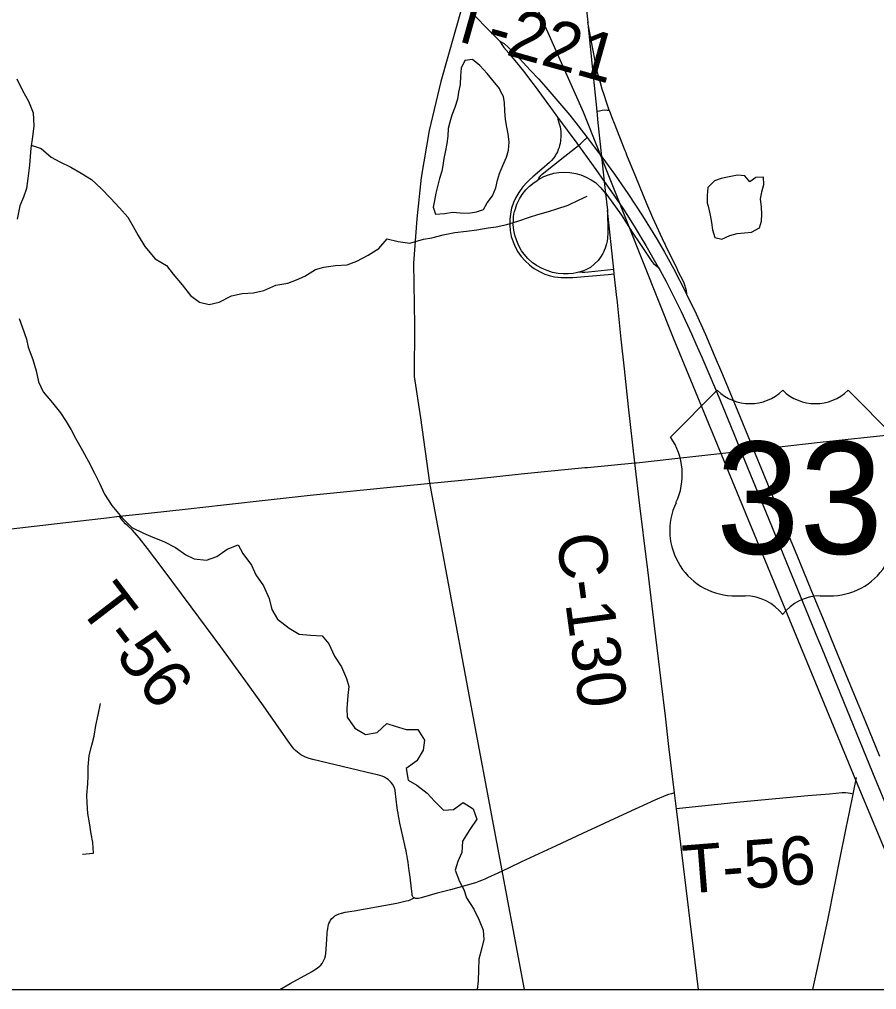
# Model space of a CAD drawing. Extents: x -5.9 to 34, y 0 to 22.
# Drawn here: x 5.923 to 7.938, y 14 to 16.281 of the extents above; entities that cross this region are included whole.
import ezdxf

# ---------------------------------------------------------------- set-up
doc = ezdxf.new("R2010")
doc.units = 0
for name, color, linetype in [('GM_X_County_Road', 7, 'Continuous'), ('GM_X_County_Road_Text', 7, 'Continuous'), ('GM_X_Interchange_Ramps', 7, 'Continuous'), ('GM_X_Minor_Lake', 7, 'Continuous'), ('GM_X_Minor_River', 7, 'Continuous'), ('GM_X_Rail_Line', 7, 'Continuous'), ('GM_X_State_Route', 7, 'Continuous'), ('GM_X_Township_Road', 7, 'Continuous'), ('GM_X_Township_Road_Text', 7, 'Continuous'), ('GM_X_US_Route', 7, 'Continuous'), ('GM_X_US_Shield', 7, 'Continuous'), ('SH_Data', 7, 'Continuous')]:
    doc.layers.add(name, color=color, linetype=linetype)

msp = doc.modelspace()

# ---------------------------------------------------------------- linework, layer by layer
at = {"layer": 'GM_X_County_Road'}
msp.add_line((7.4675, 14.4252), (7.463, 14.4624), dxfattribs=at)
for points in [[(7.3278, 15.6228), (7.3274, 15.6268), (7.3213, 15.6824), (7.3203, 15.6929), (7.3054, 15.8323)], [(7.3449, 15.4594), (7.3371, 15.5291), (7.3278, 15.6228)], [(7.3982, 15.0005), (7.3977, 15.0045), (7.3809, 15.1377), (7.3696, 15.2383), (7.3548, 15.3698), (7.3449, 15.4594)], [(7.6189, 15.2659), (7.6487, 15.269), (7.709, 15.2759), (7.8054, 15.287), (7.9228, 15.2994), (8.0205, 15.3095), (8.0959, 15.3177), (8.1247, 15.321)], [(7.2522, 15.2272), (7.2582, 15.2278), (7.3696, 15.2383), (7.3732, 15.2386), (7.4633, 15.2489), (7.6189, 15.2659)], [(5.9038, 15.0835), (6.0323, 15.0983), (6.1212, 15.1086), (6.158, 15.1127), (6.2262, 15.1203), (6.32, 15.1306), (6.4028, 15.1399), (6.5151, 15.1521), (6.6066, 15.1621), (6.7945, 15.1809), (7.0023, 15.2017), (7.1024, 15.2123), (7.2522, 15.2272)], [(7.463, 14.4624), (7.4498, 14.5716), (7.4415, 14.6432), (7.4316, 14.7258), (7.4158, 14.8553), (7.3982, 15.0005)], [(7.7881, 14), (7.8016, 14.0615), (7.8121, 14.1126), (7.8229, 14.1636), (7.8398, 14.2464), (7.8522, 14.3098), (7.8662, 14.3792), (7.8743, 14.4169), (7.8827, 14.4596), (7.8906, 14.499)], [(7.519, 14), (7.4996, 14.1609), (7.487, 14.2645), (7.4775, 14.3422), (7.4675, 14.4252)]]:
    msp.add_lwpolyline(points, dxfattribs=at)
at = {"layer": 'GM_X_Interchange_Ramps'}
for points in [[(7.3096, 16.0674), (7.3028, 16.0861), (7.2971, 16.1039), (7.2929, 16.1169), (7.2887, 16.1317), (7.2851, 16.1443), (7.282, 16.1562), (7.2793, 16.169), (7.2765, 16.1819), (7.2747, 16.1915), (7.2724, 16.2037), (7.2701, 16.2156), (7.2588, 16.2743)], [(7.1881, 16.0509), (7.1887, 16.046), (7.1899, 16.0406), (7.1924, 16.0331), (7.1937, 16.0285), (7.1949, 16.0231), (7.1955, 16.0175), (7.1958, 16.012), (7.1959, 16.0063), (7.195, 15.9952), (7.194, 15.989), (7.1928, 15.9842), (7.1915, 15.9796), (7.1897, 15.9748), (7.1877, 15.9699), (7.1855, 15.9658), (7.1823, 15.9604), (7.1788, 15.9553), (7.1735, 15.9489), (7.1689, 15.9443), (7.151, 15.9289), (7.1301, 15.9111), (7.1222, 15.904), (7.1167, 15.8982), (7.1059, 15.8862), (7.0971, 15.8742), (7.09, 15.8625), (7.0843, 15.8501), (7.0799, 15.8372), (7.077, 15.8238), (7.0755, 15.8103), (7.0754, 15.7966), (7.0766, 15.7842), (7.0792, 15.7708), (7.0832, 15.7577), (7.088, 15.7463), (7.0946, 15.7343), (7.1025, 15.7232), (7.1116, 15.713), (7.1217, 15.7038), (7.1273, 15.6995), (7.1327, 15.6956), (7.1387, 15.692), (7.1455, 15.688), (7.1579, 15.6823), (7.1685, 15.6787), (7.1806, 15.6757), (7.1882, 15.6745), (7.1954, 15.6739), (7.2033, 15.6738), (7.2127, 15.6738), (7.2242, 15.6744), (7.307, 15.6812), (7.3213, 15.6824)], [(7.1414, 15.9033), (7.144, 15.9078), (7.1461, 15.911), (7.1483, 15.9137), (7.1519, 15.917), (7.2048, 15.9593), (7.237, 15.9845), (7.241, 15.9877), (7.2441, 15.9905), (7.2482, 15.9945), (7.2572, 16.0033)], [(7.3203, 15.6929), (7.2607, 15.6865), (7.2519, 15.6857), (7.2454, 15.6856), (7.2383, 15.6867)]]:
    msp.add_lwpolyline(points, dxfattribs=at)
at = {"layer": 'GM_X_Minor_Lake'}
for points in [[(7.0549, 16.1107), (7.0511, 16.1182), (7.0362, 16.1366), (7.0228, 16.1535), (7.0049, 16.1721), (6.9877, 16.1868), (6.9702, 16.184), (6.9616, 16.1666), (6.9598, 16.1477), (6.9588, 16.1279), (6.9554, 16.1098), (6.9529, 16.0931), (6.9466, 16.0734), (6.9395, 16.0561), (6.9347, 16.0394), (6.9307, 16.0243), (6.9297, 16.0061), (6.9279, 15.9894), (6.9238, 15.969), (6.9205, 15.9538), (6.918, 15.9371), (6.9163, 15.9243)], [(6.9163, 15.9243), (6.9107, 15.9069), (6.9059, 15.888), (6.9019, 15.8721), (6.8986, 15.8554), (6.8953, 15.8395), (6.9012, 15.8227), (6.9224, 15.8247), (6.9414, 15.8274), (6.9588, 15.8264), (6.9785, 15.8253), (6.9975, 15.8281), (7.0135, 15.8339), (7.0221, 15.8497), (7.0352, 15.8662), (7.043, 15.8851), (7.0471, 15.9032), (7.0511, 15.9184), (7.059, 15.9372), (7.0676, 15.9569), (7.0724, 15.9735), (7.0742, 15.9925), (7.0722, 16.0115), (7.0687, 16.0275), (7.0659, 16.0458), (7.0639, 16.0656), (7.0634, 16.0845), (7.0606, 16.0998), (7.0549, 16.1107)], [(7.6672, 15.8707), (7.6681, 15.8754), (7.6729, 15.8928), (7.6717, 15.9103), (7.6542, 15.9091), (7.6397, 15.8987), (7.6278, 15.9133), (7.6111, 15.9143), (7.5914, 15.9108), (7.5724, 15.9065), (7.5564, 15.9015), (7.541, 15.8857), (7.5399, 15.8668), (7.5397, 15.8493), (7.5416, 15.8418)], [(7.5416, 15.8418), (7.5468, 15.8203), (7.5496, 15.8036), (7.5524, 15.7861), (7.5574, 15.7685), (7.574, 15.7645), (7.5931, 15.7725), (7.6098, 15.7776), (7.6273, 15.7788), (7.644, 15.7808), (7.6623, 15.7912), (7.6671, 15.8063), (7.6681, 15.823), (7.6676, 15.8397), (7.6649, 15.8588), (7.6672, 15.8707)]]:
    msp.add_lwpolyline(points, dxfattribs=at)
at = {"layer": 'GM_X_Minor_River'}
for points in [[(5.9172, 16.1412), (5.9303, 16.1137), (5.9443, 16.0884), (5.9552, 16.0609), (5.957, 16.0305), (5.9535, 16.0047), (5.9501, 15.9782), (5.9482, 15.9585), (5.9471, 15.938), (5.9428, 15.907), (5.9394, 15.8835), (5.9323, 15.8631), (5.9244, 15.8428), (5.9178, 15.811)], [(5.951, 15.9853), (5.9743, 15.977), (5.9974, 15.9569), (6.0184, 15.9459), (6.0439, 15.9334), (6.0679, 15.9193), (6.0927, 15.9045), (6.115, 15.8836), (6.1373, 15.8604), (6.1582, 15.8381), (6.1782, 15.8157), (6.1908, 15.7943), (6.2025, 15.7728), (6.218, 15.7467), (6.2425, 15.7182), (6.2687, 15.7026), (6.2843, 15.6819), (6.3058, 15.6572), (6.3251, 15.6318), (6.346, 15.6163), (6.3694, 15.6106), (6.3929, 15.6163), (6.4219, 15.631), (6.447, 15.6366), (6.4735, 15.6377), (6.4978, 15.6434), (6.526, 15.6558), (6.5541, 15.6606), (6.5747, 15.6686), (6.5938, 15.6774), (6.619, 15.6929), (6.6388, 15.6987), (6.6661, 15.702), (6.6933, 15.7038), (6.7162, 15.7125), (6.7429, 15.7265), (6.7681, 15.742), (6.7874, 15.7652), (6.8131, 15.7587), (6.841, 15.7545), (6.8729, 15.7645), (6.8927, 15.7673), (6.9193, 15.7744), (6.9466, 15.78), (6.9739, 15.7833), (6.9982, 15.786), (7.0247, 15.7908), (7.0437, 15.7935), (7.0688, 15.7984), (7.0946, 15.8063), (7.122, 15.8158), (7.1418, 15.8222), (7.1669, 15.8294), (7.1859, 15.8359), (7.2125, 15.8438), (7.2385, 15.8563), (7.2576, 15.8651)], [(5.9223, 15.5779), (5.9296, 15.558), (5.9397, 15.529), (5.9439, 15.51), (5.9548, 15.4817), (5.9627, 15.455), (5.9683, 15.4291), (5.9785, 15.4054), (6.0008, 15.3792), (6.0193, 15.3561), (6.0326, 15.3354), (6.0444, 15.3163), (6.0547, 15.2963), (6.0716, 15.2672), (6.0856, 15.2412), (6.0995, 15.2144), (6.1112, 15.1907), (6.1229, 15.1647), (6.1406, 15.1378), (6.1636, 15.1101), (6.1875, 15.0862), (6.2145, 15.0728), (6.237, 15.0633), (6.2626, 15.0538), (6.2896, 15.0397), (6.3143, 15.0218), (6.3338, 15.0124), (6.3625, 15.0096), (6.3869, 15.0183), (6.4114, 15.0353), (6.4373, 15.0455), (6.4483, 15.0249), (6.4683, 14.998), (6.4785, 14.975), (6.497, 14.9489), (6.5101, 14.9191), (6.5165, 14.8932), (6.5298, 14.8709), (6.5567, 14.85), (6.5807, 14.8352), (6.6071, 14.8332), (6.6343, 14.832)], [(6.6343, 14.832), (6.6507, 14.8127), (6.6638, 14.7837), (6.6801, 14.7591), (6.6917, 14.7316), (6.6975, 14.7125), (6.6948, 14.6913), (6.6928, 14.661), (6.6932, 14.6405), (6.7117, 14.6144), (6.7365, 14.5996), (6.7638, 14.6044), (6.7868, 14.6253), (6.8064, 14.6196), (6.832, 14.6116), (6.8593, 14.6112), (6.8748, 14.5866), (6.8721, 14.5631), (6.8573, 14.5376), (6.832, 14.5198), (6.8369, 14.4924), (6.8571, 14.4807), (6.8818, 14.4621), (6.8989, 14.4428), (6.9197, 14.422), (6.9432, 14.4231), (6.9662, 14.4401), (6.9894, 14.4253), (6.9981, 14.4009), (6.9818, 14.3761), (6.9647, 14.3491), (6.9627, 14.3226), (6.9533, 14.3015), (6.9476, 14.2811), (6.9578, 14.2544), (6.9673, 14.2352), (6.9738, 14.2154), (6.9908, 14.1893), (7.004, 14.1633), (7.0127, 14.1396), (7.0146, 14.1176), (7.0097, 14.0979), (7.0032, 14.0715), (7.002, 14.0465), (7.0016, 14.0207), (6.9988, 14)], [(6.0711, 14.3186), (6.0969, 14.3204), (6.0958, 14.3455), (6.0916, 14.366), (6.0875, 14.3919), (6.084, 14.414), (6.0822, 14.4383), (6.0817, 14.4573), (6.0837, 14.4838), (6.0848, 14.5027), (6.0844, 14.524), (6.0871, 14.5505), (6.0935, 14.5747), (6.0984, 14.5959), (6.1026, 14.6208), (6.1083, 14.6458), (6.1133, 14.6723)]]:
    msp.add_lwpolyline(points, dxfattribs=at)
at = {"layer": 'GM_X_Rail_Line'}
for points in [[(7.0415, 16.5495), (6.963, 16.3092), (6.9134, 16.1347), (6.8861, 16.02), (6.8674, 15.9094), (6.8568, 15.8119), (6.8493, 15.7081), (6.852, 15.5617), (6.8512, 15.4414), (6.8655, 15.3442), (6.8872, 15.1912), (6.9793, 14.6929), (7.1092, 14)], [(7.0415, 16.5495), (7.1132, 16.3672), (7.2481, 16.0636), (7.4593, 15.532), (7.8977, 14.4706), (8.0854, 14.0203), (8.0937, 14)]]:
    msp.add_lwpolyline(points, dxfattribs=at)
at = {"layer": 'GM_X_State_Route'}
for points in [[(7.2497, 16.3582), (7.2588, 16.2743), (7.2591, 16.2715), (7.2702, 16.1627), (7.2801, 16.0651), (7.2829, 16.0378), (7.2914, 15.9583), (7.2977, 15.8999), (7.3009, 15.8715), (7.3054, 15.8323)], [(7.2801, 16.0651), (7.2861, 16.0662), (7.2929, 16.0675), (7.2986, 16.0681), (7.3046, 16.0677), (7.3096, 16.0674), (7.3181, 16.044), (7.3194, 16.0405), (7.3209, 16.0368), (7.3462, 15.9723), (7.348, 15.9677), (7.3503, 15.9622), (7.3714, 15.9114), (7.3973, 15.8482), (7.4114, 15.815), (7.4387, 15.7558), (7.4405, 15.7518), (7.4418, 15.749), (7.4681, 15.695), (7.4717, 15.6875), (7.4766, 15.6776), (7.4836, 15.664), (7.4866, 15.6568), (7.4887, 15.6494), (7.4899, 15.6436), (7.4913, 15.6349)], [(7.2959, 15.7339), (7.2942, 15.7303), (7.2892, 15.7217), (7.2832, 15.7138), (7.2743, 15.7051), (7.265, 15.6979), (7.2543, 15.6922), (7.2462, 15.6889), (7.2383, 15.6867), (7.2316, 15.6847), (7.2243, 15.6837), (7.2126, 15.6828), (7.2009, 15.6828), (7.1897, 15.6836), (7.1763, 15.6861), (7.1632, 15.6902), (7.1518, 15.6951), (7.1387, 15.7023), (7.1286, 15.7095), (7.1184, 15.7186), (7.1093, 15.7288), (7.1035, 15.7369), (7.0966, 15.7487), (7.0918, 15.7602), (7.0877, 15.7733), (7.0852, 15.7854), (7.0839, 15.7978), (7.084, 15.809), (7.0846, 15.8168), (7.0854, 15.8226), (7.0868, 15.8294), (7.0887, 15.8359), (7.0924, 15.8464), (7.0984, 15.8588), (7.105, 15.8693), (7.1135, 15.88), (7.1221, 15.889), (7.1327, 15.8976), (7.1414, 15.9033), (7.1431, 15.9044), (7.1555, 15.9112), (7.1663, 15.9155), (7.179, 15.9192), (7.1911, 15.9212), (7.2044, 15.9217), (7.217, 15.9207), (7.2306, 15.9187), (7.2428, 15.9154), (7.2551, 15.9102), (7.2669, 15.9039), (7.2767, 15.8971), (7.2835, 15.891), (7.29, 15.8847), (7.3006, 15.8718)], [(7.3011, 15.8713), (7.3139, 15.8546), (7.3382, 15.8204), (7.3636, 15.781), (7.3814, 15.7544), (7.4063, 15.7164), (7.4094, 15.7119), (7.4135, 15.7073), (7.4179, 15.7029), (7.421, 15.7006), (7.4245, 15.6987)], [(7.3054, 15.8323), (7.3061, 15.7793), (7.3055, 15.7669), (7.3045, 15.7597), (7.3031, 15.7535), (7.2998, 15.7428), (7.2975, 15.7375), (7.2959, 15.7339)]]:
    msp.add_lwpolyline(points, dxfattribs=at)
at = {"layer": 'GM_X_Township_Road'}
msp.add_line((7.4675, 14.4252), (7.463, 14.4624), dxfattribs=at)
for points in [[(6.8512, 14.2154), (6.8494, 14.2163), (6.848, 14.2177), (6.8469, 14.2199), (6.8463, 14.2223), (6.8459, 14.2246), (6.8435, 14.2437), (6.8405, 14.2703), (6.8395, 14.2795), (6.8387, 14.2858), (6.8378, 14.2921), (6.8366, 14.2998), (6.8354, 14.3073), (6.8343, 14.3134), (6.8331, 14.3202), (6.8319, 14.3261), (6.8305, 14.332), (6.8289, 14.3395), (6.8173, 14.3916), (6.8156, 14.4003), (6.8141, 14.4086), (6.813, 14.4151), (6.8119, 14.4221), (6.8105, 14.4332), (6.8095, 14.4411), (6.8087, 14.4469), (6.808, 14.4541), (6.8073, 14.4603), (6.8061, 14.4685), (6.8044, 14.4735), (6.8027, 14.4776), (6.7997, 14.4829), (6.7966, 14.4868), (6.7936, 14.49), (6.79, 14.4936), (6.7861, 14.4964), (6.7812, 14.4992), (6.7754, 14.5014), (6.7649, 14.5047), (6.7539, 14.5076), (6.701, 14.52), (6.6126, 14.5409), (6.6038, 14.5433), (6.5958, 14.5463), (6.589, 14.5494), (6.5845, 14.5519), (6.5804, 14.5547), (6.5765, 14.5578), (6.5723, 14.562), (6.5687, 14.5656), (6.5647, 14.5702), (6.5544, 14.5842), (6.4969, 14.6668), (6.4506, 14.7314), (6.3965, 14.8058), (6.3269, 14.8995), (6.2589, 14.9912), (6.2244, 15.0368), (6.2046, 15.0618), (6.1886, 15.0797), (6.1778, 15.0901), (6.1725, 15.0952), (6.1672, 15.1015), (6.1626, 15.1071), (6.158, 15.1127)], [(7.463, 14.4624), (7.4557, 14.4603), (7.4487, 14.4583), (7.4424, 14.4561), (7.4167, 14.4454), (7.3518, 14.4156), (7.2464, 14.3669), (7.1845, 14.338), (7.1029, 14.3004), (7.0724, 14.2858)], [(7.8827, 14.4596), (7.8766, 14.4608), (7.8711, 14.4619), (7.8644, 14.4625), (7.8567, 14.4623), (7.8273, 14.4595), (7.7765, 14.4553), (7.617, 14.4409), (7.4742, 14.4259), (7.4675, 14.4252)], [(7.0724, 14.2858), (7.0473, 14.2739), (7.0232, 14.2626), (7.0173, 14.2598), (7.0089, 14.2563), (7.0031, 14.2539), (6.9989, 14.2522), (6.9953, 14.2511), (6.9366, 14.2349), (6.905, 14.2265), (6.8675, 14.2155), (6.8641, 14.2148), (6.8608, 14.2142), (6.8587, 14.214), (6.8566, 14.2141), (6.8541, 14.2144), (6.8512, 14.2154)], [(6.5348, 14), (6.5591, 14.014), (6.6094, 14.042), (6.6169, 14.0465), (6.623, 14.0506), (6.6277, 14.0542), (6.6313, 14.0577), (6.6345, 14.0617), (6.6371, 14.066), (6.6388, 14.0691), (6.6406, 14.0735), (6.6423, 14.0792), (6.6432, 14.0847), (6.6449, 14.1059), (6.6463, 14.131), (6.6466, 14.1351), (6.647, 14.1383), (6.6476, 14.1433), (6.6487, 14.1486), (6.6498, 14.1528), (6.6507, 14.1556), (6.6523, 14.1591), (6.6545, 14.1629), (6.6575, 14.1668), (6.6609, 14.1702), (6.6647, 14.1733), (6.6692, 14.1761), (6.6745, 14.1783), (6.6803, 14.18), (6.6885, 14.1817), (6.71, 14.1855), (6.8104, 14.2032), (6.8322, 14.2084), (6.8372, 14.2097), (6.8413, 14.2112), (6.8481, 14.2141), (6.8512, 14.2154)]]:
    msp.add_lwpolyline(points, dxfattribs=at)
at = {"layer": 'GM_X_US_Route'}
for points in [[(6.9277, 16.356), (6.9823, 16.3006), (7.035, 16.247), (7.0526, 16.2296)], [(7.0526, 16.2296), (7.0571, 16.2221), (7.062, 16.215), (7.0732, 16.2016), (7.0831, 16.1894), (7.0954, 16.1745)], [(7.0526, 16.2296), (7.0622, 16.2243), (7.0725, 16.2145), (7.0982, 16.1886), (7.1234, 16.1618), (7.1431, 16.1409), (7.1602, 16.1213), (7.1793, 16.0995), (7.2164, 16.0558), (7.2364, 16.0305), (7.2572, 16.0033), (7.2743, 15.9809), (7.2914, 15.9583), (7.2945, 15.9544), (7.3068, 15.9375), (7.3216, 15.9173), (7.339, 15.8922), (7.3534, 15.8714), (7.3872, 15.8193), (7.422, 15.7634), (7.4396, 15.7335), (7.4605, 15.6954), (7.4893, 15.639), (7.4913, 15.6349), (7.5137, 15.5887), (7.5357, 15.54), (7.5563, 15.4918), (7.5758, 15.4464), (7.6115, 15.359), (7.6406, 15.2886), (7.6487, 15.269), (7.6713, 15.2142), (7.717, 15.1023), (7.7503, 15.021), (7.7904, 14.9234), (7.8144, 14.8651), (7.8397, 14.8037), (7.8599, 14.7543), (7.8802, 14.7048), (7.9115, 14.6292), (7.9447, 14.5488)], [(7.0954, 16.1745), (7.0978, 16.1716), (7.1109, 16.1556), (7.1221, 16.1407), (7.1351, 16.1234), (7.1776, 16.0651), (7.1881, 16.0509), (7.2329, 15.9901), (7.237, 15.9845), (7.2781, 15.9277), (7.2977, 15.8999), (7.3146, 15.8758), (7.3411, 15.8367), (7.3504, 15.8221), (7.3681, 15.7949), (7.382, 15.7715), (7.3957, 15.7493), (7.4245, 15.6987), (7.4293, 15.6902), (7.443, 15.6645), (7.4555, 15.64), (7.4783, 15.5944), (7.5031, 15.5414), (7.5133, 15.5184), (7.5269, 15.4869), (7.5391, 15.4592), (7.5638, 15.4009), (7.6016, 15.3093), (7.6189, 15.2659), (7.6344, 15.2271), (7.652, 15.1833), (7.6779, 15.121), (7.7989, 14.8265), (7.8079, 14.8044)], [(7.8079, 14.8044), (7.837, 14.7326), (7.9278, 14.5106), (7.9695, 14.4104), (8.0621, 14.1859), (8.1023, 14.0878), (8.1383, 14)]]:
    msp.add_lwpolyline(points, dxfattribs=at)
at = {"layer": 'GM_X_US_Shield'}
for p, q in [((7.5632, 15.4089), (7.4534, 15.2991)), ((7.9807, 15.2991), (7.8709, 15.4089)), ((7.6072, 14.9255), (7.6292, 14.9255)), ((7.8049, 14.9255), (7.8269, 14.9255))]:
    msp.add_line(p, q, dxfattribs=at)
for centre, radius, start, end in [((7.6401, 15.4874), 0.1099, 225.573, 314.427), ((7.794, 15.4874), 0.1099, 225.573, 314.427), ((7.3274, 15.2109), 0.1538, 334.5471, 35.0009), ((7.6055, 15.0793), 0.1538, 154.8319, 270.6383), ((7.8286, 15.0793), 0.1538, 269.3617, 25.1681), ((7.6292, 14.8157), 0.1099, 36.8699, 90), ((7.8049, 14.8157), 0.1099, 90, 143.1301)]:
    msp.add_arc(centre, radius, start, end, dxfattribs=at)
at = {"layer": 'SH_Data'}
msp.add_line((2, 14), (9, 14), dxfattribs=at)

# ---------------------------------------------------------------- texts
at = {"layer": 'GM_X_County_Road_Text'}
msp.add_text('C-130', height=0.11364, rotation=277.7028, dxfattribs=at).set_placement((7.1848, 15.0669))
at = {"layer": 'GM_X_Township_Road_Text'}
for s, rotation, p in [('T-221', 344.2616, (6.9257, 16.2374)), ('T-56', 307.4388, (6.0591, 14.9002)), ('T-56', 4.5881, (7.4864, 14.2251))]:
    msp.add_text(s, height=0.11364, rotation=rotation, dxfattribs=at).set_placement(p)
at = {"layer": 'GM_X_US_Shield'}
msp.add_text('33', height=0.26367, dxfattribs=at).set_placement((7.5605, 15.0244))

doc.saveas('drawing.dxf')
